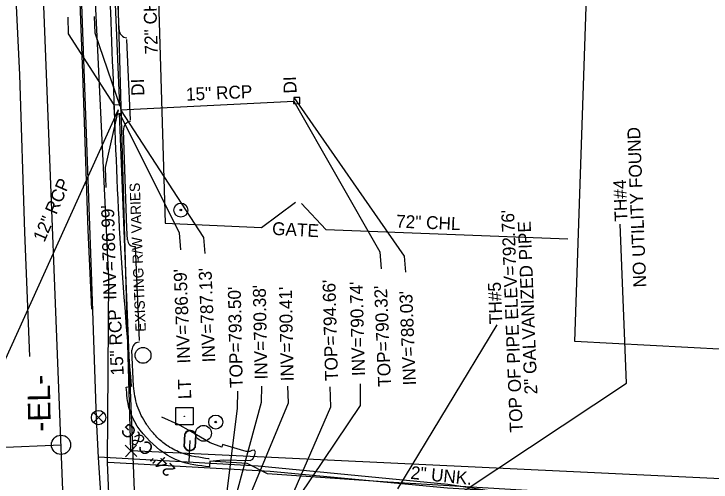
# Model space of a CAD drawing. Extents: x 1627482 to 1629573, y 760826 to 766301.
# Drawn here: x 1628398.4 to 1628615, y 763186.4 to 763332 of the extents above; entities that cross this region are included whole.
import ezdxf

# ---------------------------------------------------------------- set-up
doc = ezdxf.new("R2010")
doc.units = 0
for name, color, linetype in [('Default', 7, 'Continuous'), ('Exist Building', 7, 'Continuous'), ('Exist Horizontal Alignment', 7, 'Continuous'), ('Exist Horizontal Alignment Direction Label', 7, 'Continuous'), ('Exist Horizontal Alignment Point', 7, 'Continuous'), ('Exist Other Culture Fence Line', 7, 'Continuous'), ('Exist Other Culture Fence Line Text', 7, 'Continuous'), ('Exist Other Culture Gate', 7, 'Continuous'), ('Exist Other Culture Gate Text', 7, 'Continuous'), ('Exist Other Culture Sign CELL', 7, 'Continuous'), ('Exist Property Corner CELL', 7, 'Continuous'), ('Exist Right of Way Line', 7, 'Continuous'), ('Exist Right of Way Line Text', 7, 'Continuous'), ('Exist Roads Change in Surface', 7, 'Continuous'), ('Exist Roads Curbs', 7, 'Continuous'), ('Exist Roads Curbs Text', 7, 'Continuous'), ('Exist Roads EOP', 7, 'Continuous'), ('Exist Roads EOP Other', 7, 'Continuous'), ('Exist Roads EOT', 7, 'Continuous'), ('Exist Structure Minor Catch Basin Leader', 7, 'Continuous'), ('Exist Structure Minor Catch Basin Top Elevation', 7, 'Continuous'), ('Exist Structure Minor Drop Inlet', 7, 'Continuous'), ('Exist Structure Minor Drop Inlet Text', 7, 'Continuous'), ('Exist Structure Minor Pipes RCP 12 Inch', 7, 'Continuous'), ('Exist Structure Minor Pipes RCP 12 Inch Text', 7, 'Continuous'), ('Exist Structure Minor Pipes RCP 15 Inch', 7, 'Continuous'), ('Exist Structure Minor Pipes RCP 15 Inch Invert', 7, 'Continuous'), ('Exist Structure Minor Pipes RCP 15 Inch Leader', 7, 'Continuous'), ('Exist Structure Minor Pipes RCP 24 Inch', 7, 'Continuous'), ('Exist Utilities Gas UG Line SUE LOS B', 7, 'Continuous'), ('Exist Utilities Other Located Object CELL', 7, 'Continuous'), ('Exist Utilities Other Pole CELL', 7, 'Continuous'), ('Exist Utilities Other Pole With Base CELL', 7, 'Continuous'), ('Exist Utilities Other Pole With Base Text', 7, 'Continuous'), ('Exist Utilities Sanitary Sewer Manhole Leader', 7, 'Continuous'), ('Exist Utilities Sanitary Sewer Manhole Text', 7, 'Continuous'), ('Exist Utilities Sanitary Sewer UG Line Invert Elevation', 7, 'Continuous'), ('Exist Utilities Sanitary Sewer UG Line Leader', 7, 'Continuous'), ('Exist Utilities Water Meter CELL', 7, 'Continuous'), ('Exist Utilities Water Test Hole SUE LOS A Leader', 7, 'Continuous'), ('Exist Utilities Water Test Hole SUE LOS A Text', 7, 'Continuous'), ('Exist Utilities Water UG Line SUE LOS B', 7, 'Continuous'), ('Exist Utilities Water UG Line SUE LOS B Text', 7, 'Continuous'), ('Exist Utilities Water Valve CELL', 7, 'Continuous')]:
    doc.layers.add(name, color=color, linetype=linetype)

# ---------------------------------------------------------------- blocks, each defined once
blk = doc.blocks.new('POINT_DISPLAY')
at = {"layer": 'Default'}
blk.add_line((0, 0), (0, 0), dxfattribs=at)
blk = doc.blocks.new('EXIST PROPERTY CORNER')
at = {"layer": 'Exist Property Corner CELL'}
blk.add_lwpolyline([(-3.81, 0), (3.81, 0), (0, 0), (0, 3.81), (0, -3.81)], dxfattribs=at)
blk.add_blockref('POINT_DISPLAY', (0, 0), dxfattribs=at)

msp = doc.modelspace()

# ---------------------------------------------------------------- linework, layer by layer
at = {"layer": 'Exist Building'}
msp.add_lwpolyline([(1628572.68, 763230.13), (1628576.46, 763340.39), (1628717.21, 763335.71), (1628713.19, 763222.61)], close=True, dxfattribs=at)
at = {"layer": 'Exist Horizontal Alignment'}
for p, q in [((1628461.18, 761975.88), (1628351.56, 764755.6)), ((1628268.7, 763192.24), (1628412.99, 763197.98))]:
    msp.add_line(p, q, dxfattribs=at)
at = {"layer": 'Exist Horizontal Alignment Point'}
msp.add_circle((1628412.99, 763197.98), 3, dxfattribs=at)
at = {"layer": 'Exist Other Culture Fence Line'}
msp.add_line((1628495.28, 763264.94), (1628570.51, 763262), dxfattribs=at)
msp.add_lwpolyline([(1628443.07, 763343.38), (1628445.39, 763266.88), (1628475.27, 763265.61)], dxfattribs=at)
at = {"layer": 'Exist Other Culture Gate'}
for p, q in [((1628475.27, 763265.61), (1628485.84, 763273.44)), ((1628487.7, 763273.08), (1628495.28, 763264.94))]:
    msp.add_line(p, q, dxfattribs=at)
at = {"layer": 'Exist Other Culture Sign CELL'}
for radius in [2.18, 0.24]:
    msp.add_circle((1628450.23, 763270.98), radius, dxfattribs=at)
at = {"layer": 'Exist Right of Way Line'}
for points in [[(1628434.73, 763196.09), (1628430.42, 763347.46)], [(1628775.4, 763179.95), (1628434.73, 763196.09)]]:
    msp.add_lwpolyline(points, dxfattribs=at)
at = {"layer": 'Exist Roads Change in Surface'}
msp.add_line((1628436.07, 763259.67), (1628437.32, 763230.45), dxfattribs=at)
at = {"layer": 'Exist Roads Curbs'}
for p, q in [((1628431.07, 763327.09), (1628430.17, 763349.95)), ((1628433.47, 763324.57), (1628433.48, 763324.57)), ((1628434.65, 763298.64), (1628434.71, 763298.63)), ((1628433.47, 763265.41), (1628432.39, 763295.81)), ((1628433.67, 763261.73), (1628433.47, 763265.41)), ((1628436.07, 763259.67), (1628436.08, 763259.7)), ((1628437.27, 763229.94), (1628437.24, 763229.97)), ((1628435.5, 763216.24), (1628435.05, 763227.42)), ((1628444.26, 763206.72), (1628449.34, 763204.37)), ((1628458.96, 763193.65), (1628459, 763193.62)), ((1628459.22, 763192.87), (1628463.43, 763193.35))]:
    msp.add_line(p, q, dxfattribs=at)
msp.add_lwpolyline([(1628463.43, 763193.35), (1628471.82, 763193.13), (1628472.64, 763193.53), (1628473.18, 763194.69), (1628473.39, 763195.69), (1628473.09, 763196.29), (1628472.34, 763196.25), (1628471.64, 763195.89), (1628470.55, 763195.88), (1628463.15, 763198.12), (1628462.96, 763197.25), (1628459.33, 763198.64), (1628453.29, 763202.12), (1628449.34, 763204.37)], dxfattribs=at)
for centre, major_axis, ratio, start_param, end_param in [((1628433.58, 763327.08), (2.49, 0.39), 0.998152, 2.982936, 4.513938), ((1628435.09, 763295.97), (-2.46, 1.14), 0.998841, 5.311979, 6.777157), ((1628435.75, 763261.75), (1.42, -1.52), 0.999576, 3.97358, 5.691464), ((1628437.5, 763227.5), (-2.44, 0.28), 0.999176, 4.923355, 6.430717)]:
    msp.add_ellipse(centre, major_axis=major_axis, ratio=ratio, start_param=start_param, end_param=end_param, dxfattribs=at)
msp.add_spline([(1628459, 763193.62), (1628450.61, 763195.38), (1628446.3, 763197.52), (1628443.17, 763200), (1628441.7, 763201.56), (1628439.55, 763204.37), (1628436.71, 763210.13), (1628435.5, 763216.24)], degree=3, dxfattribs=at)
at = {"layer": 'Exist Roads EOP'}
msp.add_line((1628433.28, 763215.95), (1628434.9, 763216.21), dxfattribs=at)
msp.add_lwpolyline([(1628563.09, 763183.45), (1628514.59, 763186.36), (1628477.19, 763188.93), (1628470.8, 763192.21), (1628459.22, 763192.87), (1628459.17, 763191.1)], dxfattribs=at)
for points in [[(1628434.9, 763216.21), (1628431.21, 763265.32), (1628429.16, 763314.13), (1628427.18, 763363.32), (1628425.04, 763421.76), (1628423.32, 763462.76), (1628421.43, 763513.13), (1628419.57, 763562.9), (1628417.6, 763612.23), (1628415.46, 763663.05), (1628413.54, 763712.09), (1628411.66, 763761.59), (1628409.65, 763812), (1628409, 763828.79), (1628409.61, 763834.38), (1628410.87, 763837.96)], [(1628459.17, 763191.1), (1628449.63, 763193.02), (1628440.58, 763199.13), (1628434.2, 763209.23), (1628433.28, 763215.95)]]:
    msp.add_spline(points, degree=3, dxfattribs=at)
at = {"layer": 'Exist Roads EOP Other'}
msp.add_lwpolyline([(1628434.62, 763299.06), (1628433.91, 763314.61), (1628433.42, 763324.03)], dxfattribs=at)
at = {"layer": 'Exist Roads EOT'}
for points in [[(1628377.87, 763859.5), (1628380.23, 763810.75), (1628382.07, 763760.7), (1628383.93, 763711.23), (1628385.89, 763662.18), (1628387.8, 763610.99), (1628389.77, 763561.21), (1628391.71, 763511.55), (1628393.5, 763461.6), (1628395.57, 763412.34), (1628397.69, 763362.37), (1628400.06, 763313.06), (1628401.63, 763264.1), (1628403.18, 763225.5)], [(1628398.54, 763859.58), (1628400.24, 763811.28), (1628400.24, 763811.31), (1628402.28, 763761), (1628404.26, 763711.26), (1628406.21, 763662.3), (1628407.96, 763611.4), (1628409.93, 763561.99), (1628411.82, 763511.59), (1628413.96, 763462.19), (1628417.79, 763363.34), (1628419.64, 763313.54), (1628421.3, 763264.76), (1628422.48, 763240.19)]]:
    msp.add_lwpolyline(points, dxfattribs=at)
at = {"layer": 'Exist Structure Minor Catch Basin Leader'}
for points in [[(1628485.37, 763304.87), (1628512.06, 763258.05), (1628512.47, 763252.7)], [(1628431.22, 763301.11), (1628449.72, 763263.93), (1628450.12, 763258.58)], [(1628461.95, 763161.8), (1628467.83, 763209.35), (1628467.9, 763214.71)]]:
    msp.add_lwpolyline(points, dxfattribs=at)
at = {"layer": 'Exist Structure Minor Drop Inlet'}
msp.add_lwpolyline([(1628485.38, 763306.03), (1628485.27, 763304.13), (1628487.21, 763304), (1628487.22, 763306.03)], close=True, dxfattribs=at)
msp.add_lwpolyline([(1628429.66, 763300.75), (1628429.55, 763303.74), (1628429.55, 763303.74), (1628431.49, 763303.8), (1628431.62, 763300.77), (1628429.71, 763300.73)], dxfattribs=at)
at = {"layer": 'Exist Structure Minor Pipes RCP 12 Inch'}
msp.add_line((1628430.76, 763302.17), (1628392.89, 763218.52), dxfattribs=at)
at = {"layer": 'Exist Structure Minor Pipes RCP 15 Inch'}
for p, q in [((1628431.44, 763302.2), (1628485.37, 763304.87)), ((1628437.73, 763134.47), (1628431.22, 763301.11))]:
    msp.add_line(p, q, dxfattribs=at)
at = {"layer": 'Exist Structure Minor Pipes RCP 15 Inch Leader'}
for points in [[(1628429.55, 763303.74), (1628415.34, 763325.81), (1628415.18, 763330.99)], [(1628431.35, 763303.31), (1628423.61, 763326.02), (1628423.45, 763331.2)], [(1628485.38, 763306.03), (1628519.68, 763256.62), (1628520.09, 763251.63)], [(1628430.76, 763302.17), (1628426.67, 763284.25), (1628426.94, 763278.01)], [(1628431.44, 763302.2), (1628457.33, 763262.5), (1628457.74, 763257.51)], [(1628462.15, 763162.71), (1628475.34, 763211.25), (1628475.44, 763216.25)], [(1628463.26, 763161.86), (1628483.69, 763211.09), (1628483.53, 763216.27)]]:
    msp.add_lwpolyline(points, dxfattribs=at)
at = {"layer": 'Exist Structure Minor Pipes RCP 24 Inch'}
msp.add_lwpolyline([(1628431.28, 763303.29), (1628426.71, 763410.81)], dxfattribs=at)
msp.add_lwpolyline([(1628431.28, 763303.29), (1628426.71, 763410.81)], dxfattribs=at)
at = {"layer": 'Exist Utilities Gas UG Line SUE LOS B'}
for points in [[(1628455.93, 762522.59), (1628454.86, 762540.58), (1628450.29, 762658.27), (1628443.47, 762749.99), (1628439.81, 762852.17), (1628438.59, 762940.39), (1628435.05, 763028.04), (1628431.89, 763086.26), (1628429.39, 763146.91), (1628427.42, 763192.52), (1628427.81, 763249.84), (1628422.11, 763368), (1628418.41, 763441.73), (1628413.99, 763549.83), (1628410.61, 763659.76)], [(1628427.64, 763192.64), (1628478.03, 763189.83), (1628533.14, 763184.56), (1628565.03, 763182.73), (1628602.18, 763179.49)]]:
    msp.add_lwpolyline(points, dxfattribs=at)
at = {"layer": 'Exist Utilities Other Located Object CELL'}
for radius in [2.18, 0.24]:
    msp.add_circle((1628461.08, 763205.07), radius, dxfattribs=at)
at = {"layer": 'Exist Utilities Other Pole CELL'}
for centre in [(1628438.49, 763225.8), (1628457.26, 763201.58)]:
    msp.add_circle(centre, 2.46, dxfattribs=at)
at = {"layer": 'Exist Utilities Other Pole With Base CELL'}
msp.add_line((1628451.35, 763206.86), (1628451.35, 763206.86), dxfattribs=at)
msp.add_lwpolyline([(1628448.63, 763209.56), (1628454.03, 763209.56), (1628454.03, 763204.16), (1628448.63, 763204.16), (1628448.63, 763209.56)], dxfattribs=at)
msp.add_circle((1628451.35, 763206.86), 0.0707, dxfattribs=at)
at = {"layer": 'Exist Utilities Sanitary Sewer Manhole Leader'}
msp.add_lwpolyline([(1628482.38, 763176.39), (1628496.89, 763209.83), (1628496.7, 763216.07)], dxfattribs=at)
at = {"layer": 'Exist Utilities Sanitary Sewer UG Line Leader'}
msp.add_lwpolyline([(1628483.28, 763176.31), (1628506.12, 763210.26), (1628506.06, 763216.98)], dxfattribs=at)
at = {"layer": 'Exist Utilities Water Meter CELL'}
for q in [(1628452.7, 763192.67), (1628453.08, 763199.3)]:
    msp.add_line((1628453.08, 763199.3), q, dxfattribs=at)
for points in [[(1628451.28, 763197.35), (1628451.5, 763201.45)], [(1628451.41, 763197.35), (1628451.63, 763201.44)], [(1628454.75, 763201.25), (1628454.54, 763197.18)], [(1628454.89, 763201.24), (1628454.67, 763197.17)]]:
    msp.add_lwpolyline(points, dxfattribs=at)
for centre, radius, start, end in [((1628453.15, 763200.6), 1.86, 20.1048, 152.9061), ((1628453.15, 763200.59), 1.73, 22.2277, 150.7091), ((1628453.02, 763198.01), 1.86, 200.5751, 333.2351), ((1628453.01, 763198), 1.73, 202.0539, 331.7996)]:
    msp.add_arc(centre, radius, start, end, dxfattribs=at)
at = {"layer": 'Exist Utilities Water Test Hole SUE LOS A Leader'}
msp.add_line((1628517.7, 763184.26), (1628548.53, 763235.27), dxfattribs=at)
msp.add_lwpolyline([(1628518.26, 763170.45), (1628588.78, 763217.11), (1628586.83, 763266.63)], dxfattribs=at)
at = {"layer": 'Exist Utilities Water UG Line SUE LOS B'}
for points in [[(1628450.41, 762539.87), (1628445.25, 762659.25), (1628441.77, 762753.6), (1628437.89, 762851.35), (1628436.26, 762919.79), (1628435.73, 762936.85), (1628431.85, 763027.57), (1628429.55, 763086.45), (1628426.71, 763162.13), (1628424.64, 763194.05), (1628424.06, 763206.28), (1628422.45, 763251.82), (1628419.13, 763343.62), (1628415.44, 763443.33), (1628411.94, 763549.93), (1628407.24, 763655.16), (1628402.4, 763754.94)], [(1628424.63, 763194.29), (1628474.32, 763191.43), (1628533.26, 763185.71), (1628565.12, 763180.86), (1628602.01, 763177.75)]]:
    msp.add_lwpolyline(points, dxfattribs=at)
at = {"layer": 'Exist Utilities Water Valve CELL'}
msp.add_lwpolyline([(1628426.22, 763208.05), (1628423.07, 763204.9), (1628424.65, 763206.48), (1628426.22, 763204.9), (1628423.07, 763208.05)], dxfattribs=at)
msp.add_circle((1628424.65, 763206.48), 2.23, dxfattribs=at)

# ---------------------------------------------------------------- block references
at = {"layer": 'Exist Property Corner CELL', "xscale": 0.6561666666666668, "yscale": 0.6561666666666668, "rotation": 45.72460018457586}
msp.add_blockref('EXIST PROPERTY CORNER', (1628434.73, 763196.09), dxfattribs=at)

# ---------------------------------------------------------------- texts
at = {"layer": 'Exist Horizontal Alignment Direction Label'}
msp.add_text('-EL-', height=7, rotation=90.9545, dxfattribs=at).set_placement((1628409.81, 763202.12))
at = {"layer": 'Exist Other Culture Fence Line Text'}
for rotation, p in [(91.7333, (1628443.1, 763319.45)), (357.6792, (1628517.07, 763265.55))]:
    msp.add_text('72" CHL', height=4, rotation=rotation, dxfattribs=at).set_placement(p)
at = {"layer": 'Exist Other Culture Gate Text'}
msp.add_text('GATE', height=4, rotation=356.9745, dxfattribs=at).set_placement((1628478.52, 763263.31))
at = {"layer": 'Exist Right of Way Line Text'}
msp.add_text('EXISTING R/W VARIES', height=3.2, rotation=92.3647, dxfattribs=at).set_placement((1628439.37, 763233.21))
at = {"layer": 'Exist Roads Curbs Text'}
msp.add_text('24" C&G', height=4, rotation=135.7023, dxfattribs=at).set_placement((1628448.85, 763190.56))
at = {"layer": 'Exist Structure Minor Catch Basin Top Elevation'}
for s, rotation, p in [("INV=786.59'", 92.3486, (1628453.18, 763223.35)), ("TOP=793.50'", 91.1941, (1628469.49, 763215.71)), ("TOP=790.32'", 92.3486, (1628515.58, 763216.12))]:
    msp.add_text(s, height=4, rotation=rotation, dxfattribs=at).set_placement(p)
at = {"layer": 'Exist Structure Minor Drop Inlet Text'}
for rotation, p in [(92.2582, (1628486.24, 763307.31)), (91.5197, (1628438.89, 763306.57))]:
    msp.add_text('DI', height=4, rotation=rotation, dxfattribs=at).set_placement(p)
at = {"layer": 'Exist Structure Minor Pipes RCP 12 Inch Text'}
for s, rotation, p in [('15" RCP', 2.4981, (1628451.92, 763304.99)), ('12" RCP', 66.5445, (1628407.81, 763260.79)), ('15" RCP', 92.7462, (1628432.51, 763219.65))]:
    msp.add_text(s, height=4, rotation=rotation, dxfattribs=at).set_placement(p)
at = {"layer": 'Exist Structure Minor Pipes RCP 15 Inch Invert'}
for s, rotation, p in [("INV=786.99'", 91.5197, (1628430.23, 763243.12)), ("INV=787.13'", 92.3486, (1628460.95, 763223.72)), ("INV=790.38'", 91.1941, (1628477.21, 763218.34)), ("INV=790.41'", 91.1941, (1628485.33, 763217.78)), ("INV=788.03'", 92.3486, (1628523.34, 763216.55))]:
    msp.add_text(s, height=4, rotation=rotation, dxfattribs=at).set_placement(p)
at = {"layer": 'Exist Utilities Other Pole With Base Text'}
msp.add_text('LT', height=4, rotation=91.7713, dxfattribs=at).set_placement((1628453.49, 763212.25))
at = {"layer": 'Exist Utilities Sanitary Sewer Manhole Text'}
msp.add_text("TOP=794.66'", height=4, rotation=91.5197, dxfattribs=at).set_placement((1628499.09, 763217.89))
at = {"layer": 'Exist Utilities Sanitary Sewer UG Line Invert Elevation'}
msp.add_text("INV=790.74'", height=4, rotation=91.5197, dxfattribs=at).set_placement((1628507.49, 763219.42))
at = {"layer": 'Exist Utilities Water Test Hole SUE LOS A Text'}
for s, p in [('NO UTILITY FOUND', (1628594.93, 763247.01)), ('TH#4', (1628589.11, 763267.49)), ("TOP OF PIPE ELEV=792.76'", (1628556.52, 763201.93)), ('2" GALVANIZED PIPE', (1628561.07, 763213.75)), ('TH#5', (1628550.18, 763235.62))]:
    msp.add_text(s, height=4, rotation=92.2582, dxfattribs=at).set_placement(p)
at = {"layer": 'Exist Utilities Water UG Line SUE LOS B Text'}
msp.add_text('2" UNK.', height=4, rotation=354.2146, dxfattribs=at).set_placement((1628521.52, 763187.42))

doc.saveas('drawing.dxf')
